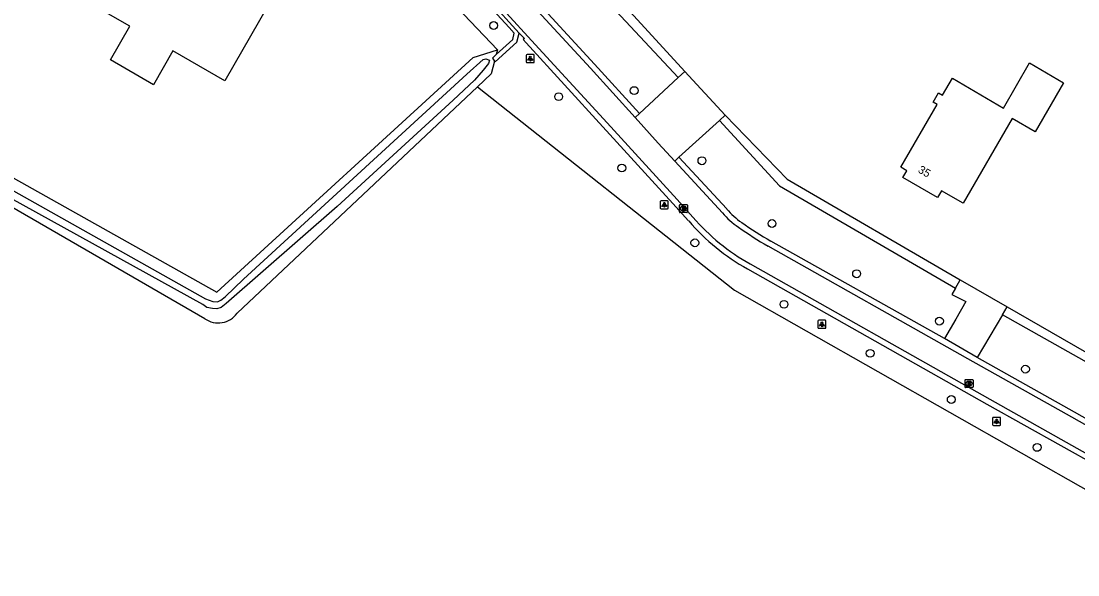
# Model space of a CAD drawing. Extents: x 156502 to 159074, y 384229 to 386094.
# Drawn here: x 157105.6 to 157237.7, y 385638.7 to 385707.8 of the extents above; entities that cross this region are included whole.
import ezdxf

# ---------------------------------------------------------------- set-up
doc = ezdxf.new("R2010")
doc.units = 0
for name, color, linetype in [('IMGEO_Berm_open', 7, 'Continuous'), ('IMGEO_Boom', 7, 'Continuous'), ('IMGEO_Erf', 7, 'Continuous'), ('IMGEO_Grasland_agrarisch', 7, 'Continuous'), ('IMGEO_Groenvoorziening', 7, 'Continuous'), ('IMGEO_Lichtpunt', 7, 'Continuous'), ('IMGEO_Pand', 7, 'Continuous'), ('IMGEO_Pand_nummerreeks', 7, 'Continuous'), ('IMGEO_Rijbaan_lokaal_halfverhard', 7, 'Continuous'), ('IMGEO_Rijbaan_lokaal_open', 7, 'Continuous'), ('IMGEO_Rioolput', 7, 'Continuous'), ('IMGEO_Waterloop', 7, 'Continuous')]:
    doc.layers.add(name, color=color, linetype=linetype)

msp = doc.modelspace()

# ---------------------------------------------------------------- linework, layer by layer
at = {"layer": 'IMGEO_Berm_open'}
for points in [[(157165.01, 385703.66), (157167.07, 385705.55), (157167.26, 385706.33), (157166.6, 385707.06), (157163.68, 385710.25), (157162.21, 385711.57), (157160.8, 385712.98)], [(157164.8, 385702.86), (157164.87, 385702.77), (157167.58, 385705.22), (157167.86, 385706.33)], [(157165.01, 385703.66), (157164.52, 385703.21), (157164.8, 385702.86)]]:
    msp.add_lwpolyline(points, dxfattribs=at)
at = {"layer": 'IMGEO_Boom'}
for centre in [(157164.68, 385707.3), (157172.8, 385698.41), (157182.24, 385699.17), (157190.71, 385690.41), (157180.7, 385689.5), (157199.47, 385682.57), (157189.83, 385680.16), (157210.04, 385676.3), (157200.97, 385672.49), (157220.39, 385670.39), (157211.73, 385666.37), (157231.14, 385664.39), (157221.87, 385660.6), (157232.6, 385654.62)]:
    msp.add_circle(centre, 0.489, dxfattribs=at)
at = {"layer": 'IMGEO_Erf'}
msp.add_lwpolyline([(157053.67, 385716.85), (157130.08, 385674.02), (157162.14, 385703.29), (157165.17, 385704.25)], dxfattribs=at)
at = {"layer": 'IMGEO_Grasland_agrarisch'}
for points in [[(157041.36, 385721.17), (157128.6, 385670.7)], [(157132.61, 385671.38), (157162.65, 385699.66)], [(157162.65, 385699.66), (157194.77, 385674.26), (157257.49, 385638.71)]]:
    msp.add_lwpolyline(points, dxfattribs=at)
msp.add_arc((157130.27, 385673.03), 2.87, 234.4827, 324.7573, dxfattribs=at)
at = {"layer": 'IMGEO_Groenvoorziening'}
for points in [[(157188.46, 385747.8), (157171.72, 385718.8), (157172.23, 385717.39), (157187.76, 385700.82)], [(157189.58, 385747.17), (157173.06, 385718.5), (157188.56, 385701.55)], [(157165.17, 385704.25), (157155.05, 385714.92), (157136.06, 385726.15)], [(157165.17, 385704.25), (157165.01, 385703.66)], [(157164.8, 385702.86), (157164.37, 385701.28), (157162.65, 385699.66)], [(157192.89, 385695.42), (157200.39, 385687.28), (157222.41, 385674.52)], [(157193.62, 385696.09), (157201.36, 385688.11), (157223, 385675.55)], [(157265.03, 385661.89), (157260.16, 385653.24), (157228.28, 385671.17)], [(157228.87, 385672.17), (157259.69, 385654.46), (157264.27, 385662.33)]]:
    msp.add_lwpolyline(points, dxfattribs=at)
at = {"layer": 'IMGEO_Lichtpunt'}
for p, q in [((157168.75, 385703.57), (157168.75, 385702.76)), ((157168.75, 385703.57), (157168.75, 385702.76)), ((157169.66, 385703.66), (157168.85, 385703.66)), ((157169.66, 385703.66), (157168.85, 385703.66)), ((157169.75, 385702.76), (157169.75, 385703.57)), ((157169.75, 385702.76), (157169.75, 385703.57)), ((157168.85, 385702.67), (157169.66, 385702.67)), ((157168.85, 385702.67), (157169.66, 385702.67)), ((157185.51, 385685.31), (157185.51, 385684.5)), ((157185.51, 385685.31), (157185.51, 385684.5)), ((157186.41, 385685.4), (157185.6, 385685.4)), ((157186.41, 385685.4), (157185.6, 385685.4)), ((157185.6, 385684.41), (157186.41, 385684.41)), ((157185.6, 385684.41), (157186.41, 385684.41)), ((157186.51, 385684.5), (157186.51, 385685.31)), ((157186.51, 385684.5), (157186.51, 385685.31)), ((157205.2, 385670.4), (157205.2, 385669.59)), ((157205.2, 385670.4), (157205.2, 385669.59)), ((157206.11, 385670.5), (157205.3, 385670.5)), ((157206.11, 385670.5), (157205.3, 385670.5)), ((157206.2, 385669.59), (157206.2, 385670.4)), ((157206.2, 385669.59), (157206.2, 385670.4)), ((157205.3, 385669.5), (157206.11, 385669.5)), ((157205.3, 385669.5), (157206.11, 385669.5)), ((157227.04, 385658.27), (157227.04, 385657.46)), ((157227.04, 385658.27), (157227.04, 385657.46)), ((157227.94, 385658.36), (157227.13, 385658.36)), ((157227.94, 385658.36), (157227.13, 385658.36)), ((157228.03, 385657.46), (157228.03, 385658.27)), ((157228.03, 385657.46), (157228.03, 385658.27)), ((157227.13, 385657.36), (157227.94, 385657.36)), ((157227.13, 385657.36), (157227.94, 385657.36))]:
    msp.add_line(p, q, dxfattribs=at)
for points in [[(157169.13, 385703.23), (157169.17, 385703.21), (157168.98, 385702.94), (157168.94, 385702.97), (157169.13, 385703.23)], [(157169.23, 385703.19), (157169.28, 385703.19), (157169.28, 385702.86), (157169.23, 385702.86), (157169.23, 385703.19)], [(157169.34, 385703.21), (157169.38, 385703.23), (157169.57, 385702.97), (157169.53, 385702.94), (157169.34, 385703.21)], [(157185.88, 385684.97), (157185.92, 385684.95), (157185.73, 385684.68), (157185.7, 385684.71), (157185.88, 385684.97)], [(157185.98, 385684.93), (157186.03, 385684.93), (157186.03, 385684.6), (157185.98, 385684.6), (157185.98, 385684.93)], [(157186.09, 385684.95), (157186.13, 385684.97), (157186.32, 385684.71), (157186.28, 385684.68), (157186.09, 385684.95)], [(157205.58, 385670.06), (157205.62, 385670.04), (157205.43, 385669.77), (157205.39, 385669.8), (157205.58, 385670.06)], [(157205.68, 385670.02), (157205.73, 385670.02), (157205.73, 385669.69), (157205.68, 385669.69), (157205.68, 385670.02)], [(157205.79, 385670.04), (157205.83, 385670.06), (157206.02, 385669.8), (157205.98, 385669.77), (157205.79, 385670.04)], [(157227.41, 385657.93), (157227.45, 385657.9), (157227.26, 385657.64), (157227.22, 385657.67), (157227.41, 385657.93)], [(157227.51, 385657.88), (157227.56, 385657.88), (157227.56, 385657.56), (157227.51, 385657.56), (157227.51, 385657.88)], [(157227.62, 385657.9), (157227.66, 385657.93), (157227.85, 385657.67), (157227.81, 385657.64), (157227.62, 385657.9)]]:
    msp.add_lwpolyline(points, dxfattribs=at)
for centre in [(157169.25, 385703.37), (157186.01, 385685.11), (157205.7, 385670.2), (157227.54, 385658.06)]:
    msp.add_circle(centre, 0.0994, dxfattribs=at)
for centre, start, end in [((157168.85, 385703.57), 90, 180), ((157168.85, 385703.57), 90, 180), ((157168.85, 385702.76), 180, 270), ((157168.85, 385702.76), 180, 270), ((157169.66, 385703.57), 0, 90), ((157169.66, 385703.57), 0, 90), ((157169.66, 385702.76), 270, 0), ((157169.66, 385702.76), 270, 360), ((157185.6, 385685.31), 90, 180), ((157185.6, 385685.31), 90, 180), ((157185.6, 385684.5), 180, 270), ((157185.6, 385684.5), 180, 270), ((157186.41, 385685.31), 0, 90), ((157186.41, 385685.31), 0, 90), ((157186.41, 385684.5), 270, 0), ((157186.41, 385684.5), 270, 360), ((157205.3, 385670.4), 90, 180), ((157205.3, 385670.4), 90, 180), ((157206.11, 385670.4), 0, 90), ((157206.11, 385670.4), 0, 90), ((157205.3, 385669.59), 180, 270), ((157205.3, 385669.59), 180, 270), ((157206.11, 385669.59), 270, 0), ((157206.11, 385669.59), 270, 360), ((157227.13, 385658.27), 90, 180), ((157227.13, 385658.27), 90, 180), ((157227.94, 385658.27), 0, 90), ((157227.94, 385658.27), 0, 90), ((157227.13, 385657.46), 180, 270), ((157227.13, 385657.46), 180, 270), ((157227.94, 385657.46), 270, 0), ((157227.94, 385657.46), 270, 360)]:
    msp.add_arc(centre, 0.0946, start, end, dxfattribs=at)
at = {"layer": 'IMGEO_Pand'}
for points in [[(157118.08, 385720.3), (157120.26, 385724.08), (157126.49, 385720.54), (157126.14, 385719.95), (157125.99, 385720.04), (157122.81, 385714.52), (157124.77, 385713.36), (157124.93, 385713.64), (157127.28, 385712.29), (157127.14, 385712.03), (157129.12, 385710.91), (157132.23, 385716.49), (157132.14, 385716.54), (157132.45, 385717.08), (157138.64, 385713.52), (157131.1, 385700.4), (157124.6, 385704.14), (157122.17, 385699.91), (157116.79, 385703), (157119.22, 385707.23), (157112.72, 385710.97), (157115.28, 385715.42)], [(157235.88, 385700.13), (157232.36, 385694.04), (157229.5, 385695.69), (157223.36, 385685.1), (157220.65, 385686.66), (157220.16, 385685.81), (157215.83, 385688.33), (157216.33, 385689.17), (157215.58, 385689.6), (157220.12, 385697.45), (157219.62, 385697.73), (157220.28, 385698.88), (157220.78, 385698.59), (157222.02, 385700.71), (157228.4, 385696.99), (157231.63, 385702.62), (157235.88, 385700.13)]]:
    msp.add_lwpolyline(points, dxfattribs=at)
at = {"layer": 'IMGEO_Rijbaan_lokaal_halfverhard'}
for points in [[(157182.89, 385696.29), (157177.3, 385702.46), (157166.19, 385714.52)], [(157167.86, 385706.33), (157164.16, 385710.4), (157163.89, 385710.68), (157163.6, 385710.91), (157163.02, 385711.44), (157162.57, 385711.84)], [(157167.86, 385706.33), (157168.52, 385705.66), (157168.38, 385705.53), (157168.76, 385705.12), (157178.32, 385694.64), (157187.07, 385685.08), (157189.05, 385682.89)], [(157193.81, 385684.39), (157187.84, 385690.85)], [(157221.01, 385668.22), (157199.33, 385680.38)], [(157196.4, 385676.91), (157226.32, 385660.03), (157240.18, 385652.26), (157255.54, 385643.57), (157256.49, 385643.05), (157257.29, 385642.57)], [(157256.7, 385648.11), (157255.85, 385648.54), (157253.23, 385650.03), (157236.62, 385659.38), (157225.12, 385665.84)]]:
    msp.add_lwpolyline(points, dxfattribs=at)
for centre, radius, start, end in [((157201.4, 385690.94), 10.03, 220.8039, 235.2419), ((157209.78, 385700.83), 27.41, 220.886, 240.7896), ((157224.45, 385723.84), 50.2, 235.0378, 239.9772)]:
    msp.add_arc(centre, radius, start, end, dxfattribs=at)
at = {"layer": 'IMGEO_Rijbaan_lokaal_open'}
for points in [[(157182.36, 385695.8), (157176.77, 385701.98), (157165.6, 385714.09)], [(157163.18, 385712.29), (157169.41, 385705.44), (157178.85, 385695.13), (157187.6, 385685.56), (157189.59, 385683.36)], [(157187.76, 385700.82), (157188.56, 385701.55)], [(157188.56, 385701.55), (157193.62, 385696.09)], [(157187.76, 385700.82), (157182.89, 385696.29)], [(157182.36, 385695.8), (157182.89, 385696.29)], [(157187.31, 385690.37), (157185.26, 385692.59), (157182.36, 385695.8)], [(157187.84, 385690.85), (157192.89, 385695.42)], [(157193.62, 385696.09), (157192.89, 385695.42)], [(157187.84, 385690.85), (157187.31, 385690.37)], [(157193.26, 385683.91), (157187.31, 385690.37)], [(157256.34, 385647.48), (157255.49, 385647.92), (157252.88, 385649.41), (157236.26, 385658.75), (157223.93, 385665.69), (157198.98, 385679.75)], [(157196.75, 385677.53), (157226.67, 385660.65), (157240.53, 385652.88), (157255.88, 385644.2), (157256.84, 385643.68), (157257.68, 385643.17)], [(157222.41, 385674.52), (157223, 385675.55)], [(157223, 385675.55), (157228.87, 385672.17)], [(157222.41, 385674.52), (157221.96, 385673.73), (157223.7, 385672.82), (157222.46, 385670.63), (157221.01, 385668.22)], [(157228.28, 385671.17), (157225.12, 385665.84)], [(157228.28, 385671.17), (157228.87, 385672.17)], [(157225.12, 385665.84), (157221.01, 385668.22)]]:
    msp.add_lwpolyline(points, dxfattribs=at)
for centre, radius, start, end in [((157209.76, 385700.82), 26.68, 220.8827, 240.8049), ((157201.4, 385690.94), 10.75, 220.8085, 235.2297), ((157224.31, 385723.63), 50.67, 235.0342, 240.0075)]:
    msp.add_arc(centre, radius, start, end, dxfattribs=at)
at = {"layer": 'IMGEO_Rioolput'}
for p, q in [((157187.9, 385684.02), (157187.9, 385684.87)), ((157187.97, 385684.94), (157188.82, 385684.94)), ((157188.38, 385684.72), (157188.41, 385684.72)), ((157188.9, 385684.87), (157188.9, 385684.02)), ((157188.82, 385683.94), (157187.97, 385683.94)), ((157188.41, 385684.16), (157188.38, 385684.16)), ((157223.66, 385663.09), (157224.51, 385663.09)), ((157223.59, 385662.17), (157223.59, 385663.02)), ((157224.51, 385662.09), (157223.66, 385662.09)), ((157224.07, 385662.87), (157224.1, 385662.87)), ((157224.1, 385662.31), (157224.07, 385662.31)), ((157224.59, 385663.02), (157224.59, 385662.17))]:
    msp.add_line(p, q, dxfattribs=at)
for points in [[(157187.9, 385684.02), (157187.9, 385684.87)], [(157187.97, 385684.94), (157188.82, 385684.94)], [(157188.48, 385684.64), (157188.23, 385684.64), (157188.23, 385684.24)], [(157188.23, 385684.24), (157188.36, 385684.24), (157188.36, 385684.41), (157188.37, 385684.41)], [(157188.41, 385684.56), (157188.36, 385684.56), (157188.36, 385684.48)], [(157188.36, 385684.48), (157188.41, 385684.48)], [(157188.41, 385684.38), (157188.49, 385684.24), (157188.62, 385684.24), (157188.56, 385684.37)], [(157188.9, 385684.87), (157188.9, 385684.02)], [(157188.82, 385683.94), (157187.97, 385683.94)], [(157223.66, 385663.09), (157224.51, 385663.09)], [(157223.59, 385662.17), (157223.59, 385663.02)], [(157224.51, 385662.09), (157223.66, 385662.09)], [(157224.17, 385662.79), (157223.92, 385662.79), (157223.92, 385662.39)], [(157223.92, 385662.39), (157224.05, 385662.39), (157224.05, 385662.55), (157224.06, 385662.55)], [(157224.1, 385662.71), (157224.05, 385662.71), (157224.05, 385662.63)], [(157224.05, 385662.63), (157224.1, 385662.63)], [(157224.1, 385662.52), (157224.18, 385662.39), (157224.31, 385662.39), (157224.25, 385662.52)], [(157224.59, 385663.02), (157224.59, 385662.17)]]:
    msp.add_lwpolyline(points, dxfattribs=at)
for centre, radius, start, end in [((157187.97, 385684.87), 0.0765, 91.552, 178.448), ((157187.97, 385684.87), 0.0765, 91.552, 178.448), ((157188.37, 385684.35), 0.0533, 26.0293, 88.6989), ((157188.42, 385684.47), 0.0964, 77.0061, 93.1865), ((157188.39, 385684.67), 0.19, 274.7715, 282.9687), ((157188.43, 385684.52), 0.0378, 276.6634, 79.6772), ((157188.48, 385684.53), 0.109, 350.3612, 89.416), ((157188.48, 385684.53), 0.112, 277.5842, 350.9817), ((157188.47, 385684.32), 0.108, 29.5134, 73.7905), ((157188.82, 385684.87), 0.0765, 1.552, 88.448), ((157188.82, 385684.87), 0.0765, 1.552, 88.448), ((157187.97, 385684.02), 0.0765, 181.552, 268.448), ((157187.97, 385684.02), 0.0765, 181.552, 268.448), ((157188.82, 385684.02), 0.0765, 271.552, 358.448), ((157188.82, 385684.02), 0.0765, 271.552, 358.448), ((157223.66, 385663.02), 0.0765, 91.552, 178.448), ((157223.66, 385663.02), 0.0765, 91.552, 178.448), ((157224.51, 385663.02), 0.0765, 1.552, 88.448), ((157224.51, 385663.02), 0.0765, 1.552, 88.448), ((157223.66, 385662.17), 0.0765, 181.552, 268.448), ((157223.66, 385662.17), 0.0765, 181.552, 268.448), ((157224.06, 385662.5), 0.0533, 26.0293, 88.6989), ((157224.11, 385662.61), 0.0964, 77.0061, 93.1865), ((157224.08, 385662.82), 0.19, 274.7715, 282.9687), ((157224.12, 385662.67), 0.0378, 276.6634, 79.6772), ((157224.17, 385662.68), 0.109, 350.3612, 89.416), ((157224.17, 385662.68), 0.112, 277.5842, 350.9817), ((157224.16, 385662.46), 0.108, 29.5134, 73.7905), ((157224.51, 385662.17), 0.0765, 271.552, 358.448), ((157224.51, 385662.17), 0.0765, 271.552, 358.448)]:
    msp.add_arc(centre, radius, start, end, dxfattribs=at)
for centre, major_axis, ratio, start_param, end_param in [((157188.38, 385684.44), (-0.387, 0.002), 0.722429, 4.712389, 7.853982), ((157188.41, 385684.44), (-0.39, 0.002), 0.717154, 1.570796, 4.712389), ((157224.07, 385662.59), (-0.387, 0.002), 0.722429, 4.712389, 7.853982), ((157224.1, 385662.59), (-0.39, 0.002), 0.717154, 1.570796, 4.712389)]:
    msp.add_ellipse(centre, major_axis=major_axis, ratio=ratio, start_param=start_param, end_param=end_param, dxfattribs=at)
at = {"layer": 'IMGEO_Waterloop'}
msp.add_lwpolyline([(157100.64, 385688.92), (157128.66, 385673.17), (157129.57, 385672.84), (157130.18, 385672.81), (157130.59, 385673.02), (157131.13, 385673.44), (157133.44, 385675.63), (157161.34, 385701.21), (157163.39, 385703.06), (157163.72, 385703.12), (157164.15, 385702.97), (157164.03, 385702.54), (157163.39, 385701.71), (157162.29, 385700.47), (157159.64, 385697.99), (157145.13, 385684.68), (157131.27, 385672.59), (157130.64, 385672.07), (157130.09, 385671.91), (157129.56, 385671.96), (157128.85, 385672.1), (157128.32, 385672.45), (157100.71, 385687.7)], dxfattribs=at)

# ---------------------------------------------------------------- texts
at = {"layer": 'IMGEO_Pand_nummerreeks'}
msp.add_text('35', height=1, rotation=329.8796, dxfattribs=at).set_placement((157217.63, 385689.02))

doc.saveas('drawing.dxf')
